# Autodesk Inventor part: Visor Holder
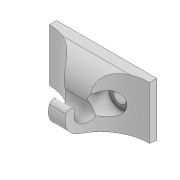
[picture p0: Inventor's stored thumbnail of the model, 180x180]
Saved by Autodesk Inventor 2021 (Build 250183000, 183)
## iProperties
Created: 2021-05
Part Number: Visor Holder
Material: Genérico
Document SubType Name: Modeling
Designer: Daniel Figueroa
Density: 1 g/cm^3
Appearance: Valor por defecto
Author: Daniel Figueroa
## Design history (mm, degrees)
sketch "Boceto1"
  geometry: C1 r 2.75 at (0, 0); C2 r 3.6 at (-18, 0); C3 r 7 at (0, 0); 1 further point
  constraints: 3 centre point, 2 coincident, 1 horizontal alignment
  dimensions: "d0" = 5.5 diameter of C1; "d1" = 18 distance of C2.centre point (0, 0); "d2" = 14 diameter of C3; "d3" = 7.2 diameter of C2
extrude "Extrusión1" new body sketch "Boceto1" distance "d4" = 4; taper "d5" = 0 deg
sketch "Boceto2"
  geometry: L1 (7.435, -11.25)-(-24.565, -11.25); L2 (-29.565, -6.25)-(-29.565, 6.25); L3 (-24.565, 11.25)-(7.435, 11.25); L4 (12.435, 6.25)-(12.435, -6.25); L5 (-24.565, -8.25)-(7.435, -8.25); L6 (9.435, -6.25)-(9.435, 6.25); L7 (7.435, 8.25)-(-24.565, 8.25); L8 (-26.565, 6.25)-(-26.565, -6.25); L9 (-19.815, -8.25)-(-16.815, -8.25); L10 (-16.815, -8.25)-(-16.815, 8.25); L11 (-16.815, 8.25)-(-19.815, 8.25); L12 (-19.815, 8.25)-(-19.815, -8.25); L13 (-11.255, -8.25)-(-8.255, -8.25); L14 (-8.565, 8.25)-(-11.255, 8.25); L15 (-0.315, -8.25)-(2.685, -8.25); L16 (2.685, -8.25)-(2.685, 8.25); L17 (2.685, 8.25)-(-0.315, 8.25); L18 (-0.315, 8.25)-(-0.315, -8.25); L19 (-10.065, -8.25)-(-7.065, -8.25); L20 (-7.065, -8.25)-(-7.065, 8.25); L21 (-7.065, 8.25)-(-10.065, 8.25); L22 (-10.065, 8.25)-(-10.065, -8.25); L23 (-19.815, 0)-(-26.565, 0); L24 (-16.815, 0)-(-10.065, 0); L25 (-7.065, 0)-(-0.315, 0); L26 (2.685, 0)-(9.435, 0); A1 r 5 centre (7.435, -6.25) between (7.435, -11.25) and (12.435, -6.25); A2 r 5 centre (-24.565, -6.25) between (-29.565, -6.25) and (-24.565, -11.25); A3 r 5 centre (-24.565, 6.25) between (-24.565, 11.25) and (-29.565, 6.25); A4 r 5 centre (7.435, 6.25) between (12.435, 6.25) and (7.435, 11.25); A5 r 2 centre (7.435, -6.25) between (7.435, -8.25) and (9.435, -6.25); A6 r 2 centre (7.435, 6.25) between (9.435, 6.25) and (7.435, 8.25); A7 r 2 centre (-24.565, 6.25) between (-24.565, 8.25) and (-26.565, 6.25); A8 r 2 centre (-24.565, -6.25) between (-26.565, -6.25) and (-24.565, -8.25); 15 further points
  constraints: 52 end point, 16 point on circle, 11 parallel, 11 point on line, 10 midpoint, 8 centre point, 8 tangent, 5 collinear, 5 horizontal, 5 perpendicular, 2 equal radius, 1 horizontal alignment, 9 other
  dimensions: "d6" = 42 distance of point (12.435, -11.25) point (-29.565, -11.25); "d7" = 22.5 distance of point (-29.565, -11.25) point (-29.565, 11.25); "d8" = 10 distance from line of L4 point (2.435, 1.278); "d9" = 5 radius of A1; "d10" = 5 radius of A2 (derived); "d11" = 3 distance between parallel lines of L1 L5; "d12" = 3 distance between parallel lines of L18 L16; "d14" = 3 distance between parallel lines of L12 L10; "d17" = 3 distance between parallel lines of L22 L20
extrude "Extrusión2" join sketch "Boceto2" distance "d18" = 3; taper "d19" = 0 deg
sketch "Boceto3"
  geometry: C1 r 7 at (0, 0) reference; C2 r 2.75 at (0, 0) reference; 1 further point
extrude "Extrusión3" cut sketch "Boceto3" stored distance "d20" = 3; taper "d21" = 0 deg
sketch "Boceto4"
  geometry: C1 r 2.75 at (0, 0); A1 r 2.75 centre (0, 0) between (0.315, -2.732) and (0.315, 2.732) reference; 1 further point
  constraints: 2 concentric, 1 centre point
extrude "Extrusión4" cut sketch "Boceto4" stored distance "d22" = 3; taper "d23" = 0 deg
sketch "Boceto5" dims "d24" = 35
  geometry: L1 (-5, 17.5)-(37, 17.5); L2 (0, 0)-(32, 0) reference; L3 (12.493, 18)-(19.507, 18); L4 (32, -3)-(0, -3) reference; L5 (0, 0)-(-5, 0) reference; L6 (37, 0)-(32, 0) reference; A1 r 17.5 centre (-5, 17.5) between (12.493, 18) and (-5, 0); 4 further points
  constraints: 4 end point, 4 horizontal, 2 midpoint, 2 vertical alignment, 1 centre point, 1 horizontal alignment, 1 point on circle, 1 tangent, 4 other
  dimensions: "d25" = 21 distance between parallel lines of L4 L3
extrude "Extrusión5" join sketch "Boceto5" stored distance "d26" = 3; taper "d27" = 0 deg
sketch "Boceto6"
  geometry: C1 r 3.6 at (0, 0) reference; 1 further point
extrude "Extrusión6" join sketch "Boceto6" distance "d28" = 6; taper "d29" = 0 deg
sketch "Boceto7"
  geometry: L1 (-37, -5)-(-37, 0) reference; L2 (5, -22.5)-(-12.5, -22.5) reference; L3 (-37, 0)-(5, 0); L4 (5, 0)-(5, -22.5); L5 (5, -22.5)-(-37, -22.5); L6 (-37, -22.5)-(-37, 0); L7 (2, -3)-(-34, -3); L8 (-34, -3)-(-34, -19.5); L9 (-34, -19.5)-(2, -19.5); L10 (2, -19.5)-(2, -3); 4 further points
  constraints: 16 end point, 4 parallel, 2 perpendicular, 1 horizontal, 3 other
  dimensions: "d30" = 3 distance between parallel lines of L3 L7
extrude "Extrusión7" join sketch "Boceto7" stored distance "d31" = 6; taper "d32" = 0 deg
sketch "Boceto8"
  geometry: L1 (21, 0)-(21, 22.5) reference; L2 (21, 22.5)-(3, 22.5) reference; L3 (0, 0)-(0, 22.5) reference; L4 (3, 22.5)-(0, 22.5) reference; L5 (4.355, 22.5)-(0, 22.5); L6 (21, 0)-(21, 8.606); L7 (21, 0)-(0, 0); A1 r 3.5 centre (14, 8.606) between (11.031, 10.46) and (17.282, 9.821); A2 r 7 centre (14, 8.606) between (14.777, 1.649) and (20.565, 11.036); A3 r 1.75 centre (18.924, 10.428) between (20.565, 11.036) and (17.282, 9.821); A4 r 1471843.752 centre (-163270.01, 1462760.04) between (0, 0) and (14.777, 1.649); A5 r 7.871 centre (4.355, 14.629) between (11.031, 10.46) and (4.355, 22.5); 1 further point
  constraints: 11 point on circle, 6 end point, 6 tangent, 5 centre point, 2 point on line, 1 horizontal, 1 perpendicular
  dimensions: "d33" = 7 diameter of A1; "d34" = 3.5 radial gap between concentric circles of A1 A2; "d36" = 1471843.75201 radius of A4
extrude "Extrusión8" cut sketch "Boceto8" stored distance "d37" = 6; taper "d38" = 0 deg
sketch "Boceto10"
  geometry: C1 r 2.75 at (0, 0) reference; 1 further point
extrude "Extrusión9" cut sketch "Boceto10" stored distance "d39" = 6; taper "d40" = 0 deg
node "Plano de trabajo1"
sketch "Boceto11"
  geometry: C1 r 2.75 at (0, 0); C2 r 2.75 at (0, 0) reference; C3 r 4.75 at (0, 0); 1 further point
  constraints: 2 centre point, 1 coincident, 1 concentric
  dimensions: "d45" = 9.5 diameter of C3
extrude "Extrusión10" cut sketch "Boceto11" distance "d43" = 16; taper "d44" = 0 deg
sketch "Boceto12"
  geometry: L1 (28.132, -9.74)-(-10.88, -9.74); L2 (-10.88, -9.74)-(-10.88, 9.947); L3 (-10.88, 9.947)-(28.132, 9.947); L4 (28.132, 9.947)-(28.132, -9.74); C1 r 2.75 at (0, 0) reference; C2 r 2.75 at (0, 0) reference; 1 further point
  constraints: 8 end point, 2 parallel, 1 horizontal, 1 perpendicular
extrude "Extrusión11" join sketch "Boceto12" stored distance "d46" = 8.25; taper "d47" = 0 deg
node "Sólido1"
node "Contorno proyectado1"
node "Contorno proyectado2"
node "Contorno proyectado3"
node "Contorno proyectado4"
other parameters: "d35" = 3.5
